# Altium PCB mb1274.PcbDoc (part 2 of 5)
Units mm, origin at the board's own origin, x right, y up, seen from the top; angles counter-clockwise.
Board outline 70 x 105 mm, 4 copper layers (Top Layer, Mid-Layer 1, Mid-Layer 2, Bottom Layer), stack 1.58 mm thick; 329 components, 271 nets, 1213 pads, 779 vias.
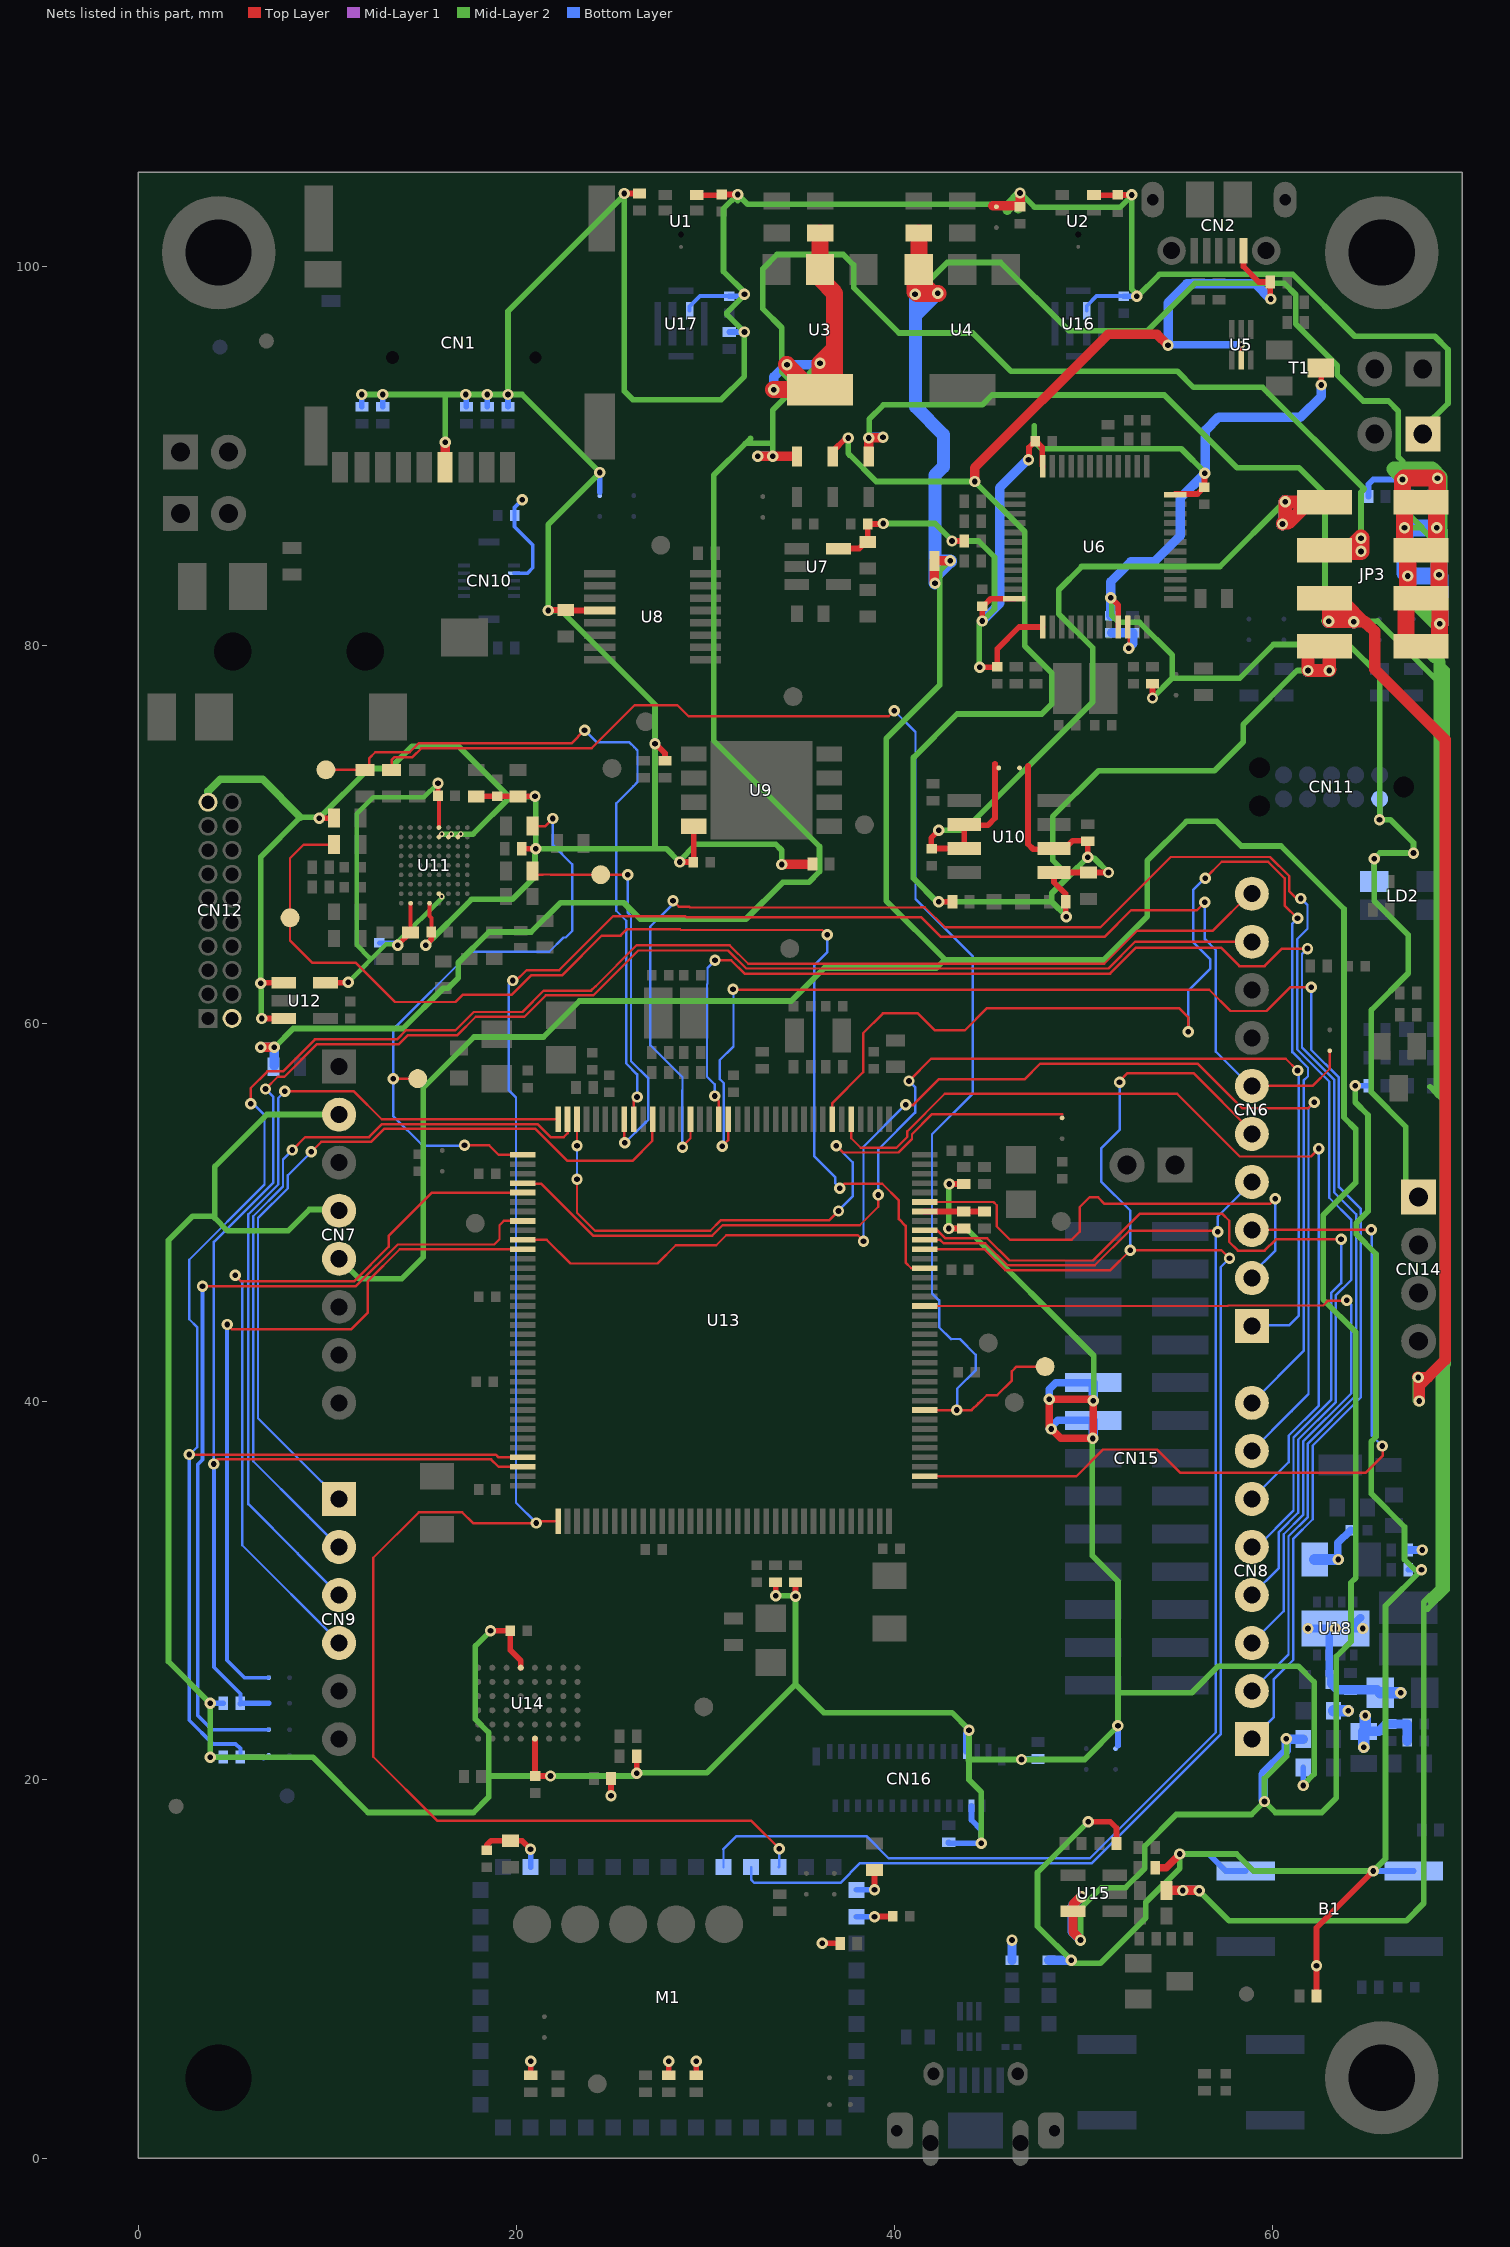
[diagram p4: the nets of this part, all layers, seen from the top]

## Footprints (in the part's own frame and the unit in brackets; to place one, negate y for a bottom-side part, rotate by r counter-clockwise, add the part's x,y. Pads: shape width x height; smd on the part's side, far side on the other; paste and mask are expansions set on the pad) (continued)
REG_SOT223-TAB [mm]
  rect 1.5x1.65 smd mask+0.05: 1(-2.3,-3.175) 2(0,-3.175) 3(2.3,-3.175)
  rect 3.5x1.65 smd mask+0.05: 4(0,3.175)
  silkscreen extent -3.35,-2.15 3.35,2.12, body extent -3.35,-3.48 3.35,3.48, height 1.8
SOLDER-BRIDGE_R0603-0R [mil]
  round 10 smd: 1(-19.69,0) 2(23.62,0)
  Top Layer region: -47.24,-19.68 -47.24,19.68 -15.75,19.68 3.94,0 -15.75,-19.68 -47.24,-19.68
  Top Layer region: -5.91,19.68 13.78,0 -5.91,-19.68 47.24,-19.68 47.24,19.68 -5.91,19.68
  silkscreen extent -50,-23 50,23, body extent -36,-20 36,20, height 22
SWI_C&K_KSC321GLFS_BLACK [mm] "BLACK"
  rect 3.1x1 smd mask+0.05: 1(-4.45,2) 2(4.45,2) 3(-4.45,-2) 4(4.45,-2)
  silkscreen extent -3.25,-3.25 3.25,3.25, body extent -5,-3.25 5,3.25, height 3.5
SWI_C&K_KSC721GLFS_BLUE [mm] "BLUE"
  rect 3.1x1 smd mask+0.05: 1(-4.45,2) 2(4.45,2) 3(-4.45,-2) 4(4.45,-2)
  silkscreen extent -3.25,-3.25 3.25,3.25, body extent -5,-3.25 5,3.25, height 4.3
TP_SMD_1MM [mm]
  round 1 smd mask+0.05: 1(0,0)
  silkscreen extent -0.7,-0.7 0.7,0.7
TP_SMD_2MM [mm]
  round 2 smd mask+0.05: 1(0,0)
  silkscreen extent -1.2,-1.2 1.2,1.2

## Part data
B1: library part Tactile_switch_CMS_BLUE_2.25N, "Tactile_switch_CMS_BLUE_2.25N"
B2: library part Tactile_switch_CMS_BLACK_2N, "Tactile_switch_CMS_BLACK_2N"
C1 C2 C7 C9 C10 C11 C12 C15 C18 C19 C25 C26 C27 C28 C29 C31 C35 C42 C50 C51 C52 C53 C54 C56 C57 C58 C59 C60 C61 C62 C63 C65 C66 C67 C68 C71 C72 C75 C77 C79 C80 C81 C82 C87 C89: library part Cap_100nF_X7R_10%_0402, "Capacitor,100nF,16V,X7R,10%,0402,YAGEO"
C3 C4 C5 C6 C88: library part Cap_10uF_X5R_10%_0805, "Capacitor,10uF,25V,X5R,10%,0805,YAGEO"
C8: library part Cap_20pF_NPO_5%_0402, "Capacitor,20pF,50V,NPO,5%,0402,YAGEO"
C13 C16 C17 C22 C23 C30 C34 C41: library part Cap_1uF_X5R_10%_0603, "Capacitor,1uF,16V,X5R,10%,0603,YAGEO"
C14: library part Cap_10nF_X7R_10%_0603, "Capacitor,10nF,50V,X7R,10%,0603,YAGEO"
C20 C21 C78 C90: library part Cap_10pF_NPO_5%_0402, "Capacitor,10pF,50V,NPO,5%,0402,YAGEO"
C24 C32 C37 C38 C39 C76: library part Cap_4.7uF_X5R_10%_0603, "Capacitor,4.7uF,16V, X5R,10%,0603,YAGEO"
C33 C36 C40 C73 C74: library part Cap_2.2uF_X5R_10%_0603, "Capacitor,2.2uF,10V, X5R,10%,0603,YAGEO"
C43 C44: library part Cap_8.2pF_NPO_4%_0402, "Capacitor,8.2pF,50V,NPO,4%,0402,AVX"
C45 C83 C86: library part Cap_10nF_X7R_10%_0402, "Capacitor,10nF,16V,X7R,10%,0402,YAGEO"
C46 C47: library part Cap_5.1pF_NPO_-+0.25pF_0402, "Capacitor, 5.1pF, 50V, NPO, -+0.25pF, 0402, YAGEO"
C48 C49 C70: library part Cap_1uF_POL_10%_TANA, "Polarized Capacitor,1uF,16V,10%,typeA,AVX"
C55 C85: library part Cap_4.7uF_POL_10%_TANA, "Polarized Capacitor,4.7uF,16V,10%,typeA,AVX"
C64 C69: library part Cap_2.2uF_X7R_10%_1206, "Capacitor,2.2uF,16V, X7R,10%,1206,YAGEO"
C84: library part Cap_4.7uF_X7R_10%_1206, "Capacitor,4.7uF,50V, X7R,10%,1206,AVX"
CN1: library part microSD-PJS008-2003, "Memory Card Connectors MicroSD Card Conn Revrs Mnt Push-Push"
CN2: library part 1050170001, "USB-MICRO-B, 1050170001, SMT, MOLEX"
CN3 CN4 CN13: library part "Header 2 pins", "Header 2 pins"
CN5: library part MCD-00263, "Connector Jack Stereo 3.5mm, female SMT, 4 PIN"
CN6: library part "Header 10X1_Female_THT", "Header, 10-Pin, Single row, female, THT, 2.54"
CN7 CN8: library part "Header 8X1_Female_THT", "Header, 8-Pins, Single row, female, THT, 2.54"
CN9: library part "Header 6X1_Female_THT", "Header, 6-Pins, Single row, female THT, 2.54"
CN10: library part "DF37NB-10DS-0.4V (5x)", "Header, 5-Pin, Dual row"
CN11: library part Tag-10-C, "Tag_Connector Header, 10-Pin, Dual row No legs"
CN12: library part "Receptacle 10X2 TH VT 1.27mm", "20 Position Receptacle Connector 0.050\" (1.27mm) Through Hole Vertical Mount"
CN14: library part "Header 4", "Header, 4-Pin"
CN15: library part "Header TMMH 13X2 2mm (.0787\")", "26 Position Receptacle Connector 0.079\" (2.00mm) Surface Mount"
CN16: library part FH26-29S-0.3SHW, "29pins FPC connector"
CN17: library part 475900001, "USB-MICRO-AB, 47590-0001, SMT, MOLEX"
D1 D2 D3 D4: library part BAT60JFILM, "BAT60JFILM"
D5: library part STPS1L40M, "Low Drop power Schottky rectifier(1A, 40V, 0.4V)"
H1 H2 H3 H4: library part "POSITION HOLE C6D3R5"
JP1 JP2: library part TSW-102-07-x-S, "Connector jumper 1 position"
JP3: library part Header_4X2_SMD, "Header, 4-Pins, Double row Vertical, SMD, 2.54"
L1 L2 L3 L5 L6 L7 L8: library part BEAD_600R_350MA_0603, "Bead,600R,350mA,0603"
L4: library part Ind_4.7uH_1A_30%, "FIXED IND 4.7UH 1A 180 MOHM 30% SMD"
LD1 LD4 LD8: library part LED_red, "LED, Red, 0603"
LD2: library part LD_BICOLOR_CMS, "Bicolor Led"
LD3 LD5 LD6 LD7: library part LED_green, "LED, Green, 0603"
M1: library part ISM43362-M3G-L44-E, "WIFI Module ISM43362-M3G-L44-E: IEEE802.11 b/g/n integrated Antenna"
R1 R2 R13 R16 R17 R20 R21 R27 R30 R31 R52 R53 R54 R55 R60 R62 R71 R72 R74 R75 R76 R77 R78 R80: library part Res_10K_1%_0402, "Resistor,10K,0402,1%,YAGEO"
R3 R14 R18 R36 R41 R70 R88 R98 R99 R100 R103 R105 R109: library part Res_100K_1%_0402, "Resistor,100K,0402,1%,YAGEO"
R4: library part Res_1K5_1%_0402, "Resistor,1K5,0402,1%,YAGEO"
R5: library part Res_36K_1%_0402, "Resistor,36K,0402,1%,YAGEO"
R6 R8: library part Res_100_1%_0402, "Resistor,100R,0402,1%,YAGEO"
R7 R51: library part Res_56_1%_0402, "Resistor,56R,0402,1%,YAGEO"
R9 R86 R87: library part Res_4K7_1%_0402, "Resistor,4K7,0402,1%,YAGEO"
R10 R56 R57 R102 R104: library part Res_2K7_1%_0402, "Resistor,2K7,0402,1%,YAGEO"
R11 R40 R44 R45 R46 R47 R48 R49 R50 R59 R61 R63 R65: library part Res_0_5%_0402, "Resistor,0R,0402,5%,YAGEO"
R12 R15 R19 R22 R23 R25 R26 R28 R29 R33 R43 R58 R67 R79: library part Res_0_5%_0603, "Resistor,0R,0603,5%,YAGEO"
R24 R39: library part Res_2K2_1%_0402, "Resistor,2K2,0402,1%,YAGEO"
R32 R35: library part Res_20_1%_0402, "Resistor,20R,0402,1%,YAGEO"
R34 R38 R93 R97 R107: library part Res_330_1%_0402, "Resistor,330R,0402,1%,YAGEO"
R37 R73 R94 R106 R108: library part Res_1K_1%_0402, "Resistor,1K,0402,1%,YAGEO"
R42 R64 R66 R68 R69 R81 R82 R83 R84 R85: library part Res_47K_1%_0402, "Resistor,47K,0402,1%,YAGEO"
R89 R90 R91 R92: library part Res_22_1%_0603, "Resistor,22R,0603,1%,Yageo"
R95: library part Res_1K_1%_0603, "Resistor,1K,0603,1%,YAGEO"
R96: library part Res_510_1%_0402, "Resistor,510R,0402,1%,YAGEO"
R101: library part Res_10_1%_0603, "Resistor,10R,0603,1%,ROHM,1/4W"
SB1 SB2 SB5 SB6 SB7 SB8 SB9 SB14 SB15 SB16 SB17 SB18 SB19 SB21 SB22: library part SB_ON, "Solder Bridge ON"
SB3 SB4 SB10 SB11 SB12 SB13 SB20 SB23 SB24: library part SB_OFF, "Solder Bridge OFF"
T1 T2 T3: library part 9013-SOT23, "NPN Bipolar Transistor"
TP1 TP2 TP3 TP4 TP5 TP6 TP7 TP8 TP9 TP10 TP11 TP12 TP13 TP14 TP15 TP16 TP22: library part "TP 1mm", "Test Point"
TP17 TP18 TP19 TP20 TP21: library part "TP 2mm", "Test Point"
U1 U2: library part MP23DB01MMTR, "MEMS audio sensor, omnidirectional digital microphone"
U3: library part LD1117S50TR, "IC REG LDO 5V 0.8A SOT223"
U4: library part LD1117S33TR, "LOW DROP FIXED AND ADJUSTABLE POSITIVE VOLTAGE REGULATORS (3.3 Volts)"
U5 U19: library part USBLC6-2P6, "USB ESD protection"
U6: library part STM32F103CBT6, "Medium-density performance line ARM-based 32-bit MCU with 128KB Flash"
U7: library part LD3985M33R, "Ultra low drop-low noise BiCMOS voltage, regulators low ESR capacitors compatible"
U8: library part TS3A44159PWR, "SPDT analog switch 4-Channel 2:1 bidirectional"
U9: library part N25Q128A13EF840F, "128Mb, 3V, Multiple I/O Serial Flash Memory, Quad/Dual"
U10: library part ST890CDR, "1.2 A current limited high-side power switch with thermal shutdown"
U11: library part WM8994ECS/R, "Multi-Channel Audio Hub CODEC for Smartphones"
U12: library part LD3985M18R, "Ultra low drop-low noise BiCMOS voltage, regulators low ESR capacitors compatible"
U13: library part STM32F413ZHT6U, "STM32 Tiny Manta 1M5 LQFP144 (STM32F413ZHT6U)"
U14: library part IS66WV51216EBLL-55BLI, "IC SRAM 8MBIT 55NS 48MINIBGA 6mm x 8mm"
U15: library part STMPS2141STR, "Enhanced single channel power switches"
U16 U17: library part MP34DT01TR-M, "MEMS audio sensor, omnidirectional digital microphone"
U18: library part STLD40DPUR, "White LED power supply for large display backlight, QFN8"
U20: library part ESDALC6V1-1U2, "Dual Transil array for ESD protection"
U21: library part MCD-00251, "High power transient voltage suppressor, 7V breakdown", Manuf_1=STM, Manuf_Part_1=ESDA7P60-1U1M
X1 X2: library part XTAL_8M_NX3225GD, "Crystal 8Mhz, 8pF, -+50PPM, SMD"
X3: library part XTAL_32K_NX3215SA, "Crystal 32.768kHz, 6pF, -+20PPM, R=50K, SMD"

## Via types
v1: diameter 0.6, hole 0.3, Top Layer to Bottom Layer, tented both sides, 574 vias
v2: diameter 0.4, hole 0.2, Top Layer to Bottom Layer, tented both sides, 125 vias
v3: diameter 0.8, hole 0.4, Top Layer to Bottom Layer, tented both sides, 49 vias
v4: diameter 0.3, hole 0.15, Top Layer to Bottom Layer, tented both sides, 31 vias

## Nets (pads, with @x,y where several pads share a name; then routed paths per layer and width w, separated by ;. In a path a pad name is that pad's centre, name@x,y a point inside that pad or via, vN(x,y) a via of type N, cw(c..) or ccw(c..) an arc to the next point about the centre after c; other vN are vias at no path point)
1V8: C26.2 C37.2 C82.2 U11.D1 U11.D8 U11.G9 U12.5 | length 27.2
  Top Layer w0.2: C37.2@14.4,64.8 U11.G9@14.4,66.35 ; U11.D8@15.9,66.85 v4(16.05,66.7) v4@16.075,66.7 ; U11.D1@15.9,70.35 C26.2@15.9,71.975
  Top Layer w0.25: v1(13.725,64.125) C37.2@14.4,64.8 ; v1(15.85,72.7) C26.2@15.85,72.025 C26.2@15.9,71.975
  Top Layer w0.3: U12.5@9.9,62.15 11.075,62.15 v1(11.1,62.175)
  Mid-Layer 1 w0.25: v1@13.725,64.1 v1(13.725,64.125)
  Mid-Layer 2 w0.25: v1(11.1,62.175) 13.1,64.175 v1@13.675,64.175 ; 12.25,63.45 11.55,64.15 11.55,71.075 12.425,71.95 15.1,71.95 v1(15.85,72.7) ; v1(13.725,64.125) 13.725,64.3 16.075,66.65 v4@16.1,66.65
  Bottom Layer w0.25: C82.2@12.75,64.25 13.6,64.25 v1(13.725,64.125)
3V3: B1.1 B1.2 C1.2 C2.2 C7.2 C16.2 C23.2 C24.2 C25.2 C28.2 C35.2 C71.2 C72.2 C73.1 C74.1 C75.2 C77.1 C79.2 C80.2 C81.1 CN1.4 CN7.2 CN7.4 CN10.9 CN12.2 CN12.19 CN15.10 CN15.12 CN16.25 CN16.26 JP2.1 L8.1 M1.2 M1.14 M1.15 R1.1 R21.2 R25.2 R30.1 R31.2 R52.2 R54.1 R56.2 R57.2 R60.2 R62.2 R64.2 R66.2 R71.2 R72.2 R74.2 R77.1 R78.1 R80.1 R81.2 R82.2 R83.2 R84.2 R85.2 R96.2 R99.2 R102.2 R103.1 R104.2 R105.1 R107.2 R108.1 SB1.2 SB14.1 SB22.1 U1.5 U2.5 U8.12 U9.8 U11.B2 U11.C2 U11.D2 U11.E9 U12.1 U12.3 U14.D6 U14.E1 U16.1 U17.1 | length 559.3
  Top Layer w0.127: v1(36.17,11.357) v1@36.177,11.35
  Top Layer w0.2: U11.E9@15.4,66.35 15.4,65.675 15.5,65.575 C35.2@15.5,64.825 ; U11.D2@15.9,69.85 v4(16.05,70) ; U11.C2@16.4,69.85 v4(16.55,70) ; U11.B2@16.9,69.85 v4(17.05,70)
  Top Layer w0.3: v1(6.475,62.125) 6.5,62.15 U12.1@7.7,62.15 ; v1(6.525,60.25) U12.3@7.7,60.25 ; v1(9.575,70.85) R25.2@10.35,70.85 ; v1(15.2,64.125) 15.5,64.425 C35.2@15.5,64.825 ; C23.2@17.875,72 C25.2@18.975,72 ; C75.2@18.425,16.275 18.425,16.55 18.65,16.775 C73.1@19.675,16.775 20.3,16.775 v1(20.74,16.335) ; v1@18.65,27.875 C71.2@19.675,27.875 ; C25.2@18.975,71.975 19,72 C24.2@20.075,72 v1(20.975,72) ; C71.2@19.675,27.85 19.675,26.85 20.225,26.3 U14.E1@20.225,25.925 ; R30.1@20.275,69.225 v1(21.025,69.225) ; R74.2@20.75,4.375 v1(20.75,5.125) ; C72.2@20.975,20.2 U14.D6@20.975,22.175 ; C72.2@21,20.2 v1(21.8,20.2) ; v1(21.675,81.825) 21.675,81.85 C16.2@22.6,81.85 ; C16.2@22.625,81.85 22.65,81.825 U8.12@24.4,81.825 ; v1(25,19.15) R62.2@25,20.075 ; v1(25.7,103.875) R1.1@26.5,103.875 ; v1(26.35,20.35) R60.2@26.35,21.25 ; v1(27.326,74.779) 27.346,74.779 27.85,74.275 R21.2@27.85,73.875 ; R77.1@28.05,4.375 v1(28.05,5.125) ; v1(28.625,68.525) C28.2@29.35,68.525 ; C28.2@29.35,68.55 29.375,68.575 U9.8@29.375,70.42 ; R78.1@29.5,4.375 v1(29.5,5.125) ; U1.5@29.538,103.789 30.839,103.789 C1.2@30.85,103.8 ; C1.2@30.85,103.825 v1(31.7,103.825) ; v1(32.052,96.555) v1@32.07,96.555 ; R56.2@33.7,30.45 33.7,29.728 v1(33.702,29.726) ; v1(34.75,29.7) R57.2@34.75,30.45 ; R31.2@35.625,68.4 R31.2@35.65,68.425 ; v1@36.177,11.35 R71.2@37.125,11.35 ; C74.1@38.925,15.225 38.925,14.191 v1(38.929,14.187) ; v1@38.937,12.775 C77.1@39.9,12.775 ; v1(42.85,49.15) R54.1@43.65,49.15 ; v1(42.875,51.5) R52.2@43.65,51.5 ; C7.2@46.525,103.225 C7.2@46.575,103.175 ; v1(50.225,17.775) 51.4,17.775 51.725,17.45 R64.2@51.725,16.625 ; U2.5@50.538,103.789 51.889,103.789 C2.2@51.9,103.8 ; C2.2@51.8,103.8 C2.2@51.9,103.8 ; v1(52.525,103.8) C2.2@51.9,103.8 ; R72.2@62.3,8.575 v1(62.3,10.175) 62.3,12.175 v1(65.3,15.175)
  Top Layer w0.4: v1@48.175,40.101 48.175,38.65 v1(48.275,38.55) 48.775,38.05 v1(50.475,38.05) ; v1(48.177,40.127) 50.423,40.127 v1@50.475,40.075 ; v1@50.45,38.075 50.5,38.125 v1(50.5,40.05) ; R66.2@53.775,15.35 54.35,15.35 v1(55.075,16.075)
  Top Layer w0.5: CN1.4@16.225,89.4 v1(16.225,90.725) ; v1(34.025,68.4) R31.2@35.625,68.4 ; 45.175,103.225 C7.2@46.525,103.225 ; C7.2@46.625,103.175 v1(46.625,103.9)
  Mid-Layer 1 w0.3: v1@33.7,29.724 v1(33.702,29.726)
  Mid-Layer 2 w0.3: v1@3.775,21.275 3.8,21.3 v1(3.8,24.05) 1.6,26.25 1.6,48.525 2.875,49.8 4.05,49.8 ; v1(3.8,21.2) 9.225,21.2 12.15,18.275 17.725,18.275 18.525,19.075 18.525,20.175 ; v1(6.475,62.125) 6.475,68.8 8.575,70.9 v1@9.55,70.9 ; v1@6.5,62.125 6.5,60.275 v1(6.525,60.25) ; v1@9.6,70.875 12.2,73.475 13.3,73.475 14.475,74.65 16.925,74.65 19.6,71.975 19.675,71.975 ; CN7.2@10.6,55.175 6.8,55.175 4.05,52.425 4.05,49.8 ; CN7.4@10.725,50.15 9.05,50.15 7.925,49.025 4.725,49.025 4.05,49.7 4.05,49.8 ; v1(11.825,93.25) v1(12.925,93.25) 16.25,93.25 ; v1(15.2,64.125) 17.625,66.55 19.775,66.55 20.975,67.75 v1@20.975,69.2 ; v4(16.05,70) v4(16.55,70) v4(17.05,70) 17.7,70 19.675,71.975 ; v1(16.225,90.725) 16.225,93.225 16.25,93.25 ; v1@17.3,93.25 16.25,93.25 ; v1(17.325,93.25) v1(18.45,93.25) v1(19.55,93.25) ; v1@18.6,27.85 17.825,27.075 17.825,23.2 18.525,22.5 18.525,20.175 ; v1@20.95,71.975 19.675,71.975 ; v1@21,69.225 v1(21.025,69.225) ; v1@21.025,71.975 v1(21.025,69.225) ; v1@24.4,89.1 21.675,86.375 v1(21.675,81.825) 22.35,81.825 27.325,76.85 v1@27.325,74.85 ; v1@24.45,89.1 20.3,93.25 v1(19.55,93.25) ; v1(25.7,103.875) 25.7,93.425 26.15,92.975 30.825,92.975 32.05,94.2 v1@32.05,96.556 ; v1@25.7,103.925 25.7,103.8 19.55,97.65 v1(19.55,93.25) ; v1@26.35,20.375 30.075,20.375 34.75,25.05 ; v1@26.375,20.425 26.15,20.2 v1(21.8,20.2) 18.55,20.2 18.525,20.175 ; v1(27.326,74.779) 27.326,69.276 27.275,69.225 ; v1@28.575,68.55 v1@28.587,68.562 ; v1(28.625,68.525) v1@28.587,68.562 ; 31.7,103.5 v1(31.7,103.825) ; v1@32.05,96.6 v1@32.05,96.556 ; v1@32.05,98.5 31.125,97.575 31.125,97.481 v1@32.05,96.556 ; v1(32.052,96.555) v1@32.05,96.556 ; v1@32.1,98.6 30.95,99.75 30.95,103.075 v1(31.7,103.825) ; v1(33.702,29.726) 34.724,29.726 v1(34.75,29.7) ; v1(34.025,68.4) 34.025,69.15 33.7,69.475 29.5,69.475 v1@28.587,68.562 ; v1@34.825,29.625 v1(34.75,29.7) ; v1@42.95,51.5 42.85,51.4 v1(42.85,49.15) 43.8,49.15 50.525,42.425 v1@50.525,40.1 ; 43.9,21.025 43.925,21.05 ; v1(44.575,16.65) 44.575,19.35 43.925,20 43.925,21.05 ; v1@46.55,103.975 45.875,103.3 32.225,103.3 v1(31.7,103.825) ; v1(46.625,103.9) 46.641,103.9 47.388,103.153 51.928,103.153 v1@52.525,103.75 ; v1(50.225,17.775) 47.55,15.1 47.55,12.25 49.5,10.3 50.875,10.3 53.275,12.7 53.275,13.525 55.075,15.325 v1(55.075,16.075) 58.075,16.075 58.975,15.175 v1(65.3,15.175) 65.95,15.825 65.95,29.2 v1(67.85,31.1) 67.5,31.1 66.95,31.65 66.95,33.375 65.201,35.124 65.201,37.891 65.45,38.14 65.45,47.8 64.4,48.85 64.4,49.434 65.025,50.059 65.025,55.15 64.35,55.825 v1(64.35,56.7) ; v1@50.45,38.125 50.45,31.85 51.8,30.5 51.8,24.6 ; v1(50.475,38.05) 50.475,39.975 v1@50.5,40 ; v1@51.825,22.85 v1@51.812,22.838 ; v1(52.525,103.8) v1@52.525,103.75 ; v1@52.575,103.8 v1@52.525,103.75 ; v1@52.8,98.4 54,99.6 61.05,99.6 64.325,96.325 68.55,96.325 69.25,95.625 69.25,92.775 67.92,91.445 JP2.1@67.92,91.15 ; v1@52.875,98.475 52.525,98.825 v1@52.525,103.75 ; v1@61.55,19.75 v1@61.625,19.75 ; v1@61.6,19.725 62.175,20.3 62.175,25.175 61.35,26 57.1,26 55.7,24.6 51.8,24.6 ; v1(21.025,69.225) 27.275,69.225 ; 27.275,69.225 27.925,69.225 v1@28.587,68.562 ; 34.75,25.05 v1(34.75,29.7) ; 34.75,25.05 36.25,23.55 43.025,23.55 43.925,22.65 v1(43.925,22.625) 43.925,21.05 ; 43.925,21.05 43.95,21.075 v1(46.7,21.075) 50.05,21.075 v1@51.812,22.838 ; 51.8,24.6 v1(51.8,22.85) v1@51.812,22.838
  Mid-Layer 2 w0.4: CN12.19@3.69,71.69 3.69,72.265 4.325,72.9 6.575,72.9 8.575,70.9
  Mid-Layer 2 w0.5: 45.95,103 v1@46.625,103.675 ; 46.525,103.075 46.625,103.175 v1@46.625,103.675 ; v1(46.625,103.9) v1@46.625,103.675
  Bottom Layer w0.127: v1(20.74,16.335) v1@20.747,16.328 ; v1@38.922,12.76 v1(38.929,12.767) ; v1@38.922,14.18 v1(38.929,14.187)
  Bottom Layer w0.2: CN10.9@19.875,83.8 20.575,83.8 20.862,84.088 20.862,85.288 19.9,86.25 C81.1@19.9,86.85 19.9,87.275 v1(20.3,87.675) v1@20.2,87.675 ; U17.1@29.15,97.675 29.15,97.9 29.7,98.45 C80.2@31.25,98.45 ; U16.1@50.15,97.675 50.15,97.925 50.675,98.45 C79.2@52.1,98.45
  Bottom Layer w0.3: v1(3.8,21.2) R104.2@4.5,21.2 ; v1(3.8,24.05) R102.2@4.5,24.05 ; R85.2@11.825,92.6 v1(11.825,93.25) ; R84.2@12.925,92.6 v1(12.925,93.25) ; v1(17.325,93.25) 17.35,93.25 R83.2@17.35,92.6 ; R82.2@18.45,92.6 v1(18.45,93.25) ; R81.2@19.55,92.6 v1(19.55,93.25) ; M1.2@20.747,15.38 v1@20.747,16.328 ; 24.4,88.075 v1(24.4,89.125) ; R80.1@31.25,96.55 32.047,96.55 v1(32.052,96.555) ; C80.2@31.25,98.45 32.05,98.45 32.052,98.452 v1(32.052,98.555) ; M1.15@37.974,12.76 v1@38.922,12.76 ; M1.14@37.974,14.18 v1@38.922,14.18 ; R105.1@42.85,16.7 42.825,16.675 42.85,16.65 v1(44.575,16.65) 44.575,17.36 44.06,17.875 CN16.26@44.06,18.625 ; CN16.25@43.76,21.5 43.76,22.435 v1@43.925,22.6 ; v1(46.7,21.075) 46.7,21.1 R103.1@47.575,21.1 ; v1(50.475,38.05) v1@50.5,38.075 ; 51.8,21.8 v1(51.8,22.85) ; C79.2@52.1,98.45 v1(52.8,98.45) ; v1(55.075,16.075) 56.6,16.075 57.5,15.175 B1.2@58.55,15.175 ; v1(61.6,19.7) L8.1@61.6,20.65 ; v1(64.35,56.7) R96.2@65.05,56.7 ; v1(65.3,15.175) B1.1@67.45,15.175 ; R99.2@67.15,31.1 v1(67.85,31.1)
  Bottom Layer w0.4: v1(48.177,40.127) 48.175,40.129 48.175,40.65 48.525,41 CN15.10@50.5,41 ; v1(48.275,38.55) 48.175,38.55 48.625,39 CN15.12@50.5,39
  Bottom Layer w0.5: R108.1@46.2,10.45 v1(46.2,11.525) ; R107.2@48.15,10.45 v1(49.325,10.45) ; v1@50.5,38.075 CN15.12@50.5,39 ; v1(50.5,40.05) CN15.10@50.5,41
  other v1: 18.625,27.875
3V3_ST_LINK: C9.2 C10.2 C12.2 C13.2 C15.2 C19.2 CN11.1 CN14.1 LD2.4 R11.2 R18.2 R87.1 T1.3 U6.1 U6.9 U6.24 U6.36 U6.48 U7.5 | length 128.1
  Top Layer w0.3: U7.5@37.025,85.1 38.125,85.1 C13.2@38.425,85.4 ; C13.2@38.575,85.45 C12.2@38.575,86.325 ; C12.2@38.575,86.4 39.375,86.4 v1(39.4,86.425) ; v1(43.025,85.5) R11.2@43.675,85.5 ; v1(44.5,78.825) 45.4,78.825 C19.2@45.425,78.85 ; v1(44.625,81.275) C15.2@44.625,82.05 ; C15.2@44.775,82.15 45.075,82.45 U6.48@46.325,82.45 ; C19.2@45.425,78.875 45.425,79.8 46.575,80.95 U6.1@47.825,80.95 ; v1@47.1,89.8 47.1,90.45 C9.2@47.425,90.775 47.425,90.825 47.793,90.457 47.793,89.482 U6.36@47.825,89.45 ; v1(51.425,82.5) 51.825,82.1 U6.9@51.825,80.95 ; v1(53.625,77.2) R18.2@53.625,77.95 ; U6.24@54.825,87.95 54.825,87.982 56.007,87.982 C10.2@56.375,88.35 56.375,89.025 v1@56.4,89.05 ; T1.3@62.525,94.65 62.55,94.625 v1(62.55,93.75)
  Mid-Layer 1 w0.3: v1(39.4,86.425) v1@39.45,86.425
  Mid-Layer 2 w0.3: v1(39.4,86.425) 42.125,86.425 v1@43.025,85.525 ; v1(43.025,85.5) 44.425,85.5 45.275,84.65 45.275,81.9 v1@44.675,81.3 ; v1@44.475,78.85 44.475,81.125 v1(44.625,81.275) ; 47.375,91.6 47.375,90.775 47.775,90.375 55.15,90.375 v1@56.425,89.1 ; v1@51.475,82.55 51.475,81.575 51.85,81.2 52.95,81.2 54.675,79.475 54.675,78.25 ; v1(53.625,77.2) 54.675,78.25 ; v1(65.635,70.76) v1@65.65,70.76 ; v1@65.65,70.75 v1@65.65,70.76 ; CN14.1@67.7,50.81 67.025,51.485 67.025,54.525 65.2,56.35 65.2,60.7 67.15,62.65 67.15,64.675 65.35,66.475 v1(65.35,68.7) 65.65,69 v1(67.425,69) 67.425,69.55 66.215,70.76 v1@65.65,70.76 ; 54.675,78.25 58.25,78.25 60.025,80.025 64,80.025 65.65,78.375 v1@65.65,70.76
  Bottom Layer w0.3: LD2.4@65.35,67.5 v1(65.35,68.7) ; v1(65.635,70.76) 65.64,70.76 CN11.1@65.64,71.865
  Bottom Layer w0.5: v1(44.625,81.275) 45.55,82.2 45.55,88.325 47.025,89.8 v1(47.075,89.8) ; R87.1@51.425,81.55 v1(51.425,82.5) 51.425,83.35 52.475,84.4 53.725,84.4 55.1,85.775 55.1,87.775 v1(56.4,89.075) ; v1@56.425,89.075 56.425,91.35 57.125,92.05 61.45,92.05 62.55,93.15 v1(62.55,93.75)
5V: C5.2 CN7.5 D4.1 JP3.2 JP3.4 JP3.6 JP3.8 L6.1 R97.1 U4.3 U15.5 | length 306.7
  Top Layer w0.3: v1(41.075,98.55) 41.175,98.6 41.135,98.63 v1@41.075,98.675 ; U4.3@41.275,99.85 U4.3@41.325,99.8 ; v1@42.93,84.455 v1(42.935,84.45) ; v1(49.825,11.525) v1@49.825,11.55 ; JP3.2@66.85,87.57 66.84,87.56 JP3.2@67.825,87.56 ; JP3.4@66.95,85.075 67.005,85.02 JP3.4@67.825,85.02 ; JP3.8@67.825,79.94 68.79,79.94 JP3.8@68.8,79.95 ; JP3.6@67.825,82.48 68.605,82.48 JP3.6@68.775,82.65 ; v1@68.8,81.125 v1(68.825,81.125)
  Top Layer w0.5: U4.3@41.075,99.65 U4.3@41.275,99.85 41.275,99.6 v1(42.275,98.6) ; v1(42.125,83.275) 42.1,83.3 D4.1@42.1,84.455 v1@42.93,84.455 ; v1@49.825,11.55 49.425,11.95 U15.5@49.425,13.05 49.425,13.4 49.85,13.825 v1(49.875,13.825)
  Top Layer w0.9: v1@41.075,98.675 U4.3@41.075,99.65 ; v1@41.175,98.6 v1(42.275,98.6) ; U4.3@41.275,99.85 C5.2@41.275,101.775 ; JP3.2@66.85,87.57 v1(66.85,88.75) 66.925,88.825 v1@68.65,88.825 ; JP3.4@66.95,85.075 v1(66.95,86.2) 66.95,87.325 JP3.2@66.975,87.35 ; JP3.6@67.025,82.45 67.025,80.05 67.05,80.025 67.74,80.025 JP3.8@67.825,79.94 ; JP3.4@67.1,84.975 67.125,84.95 v1(67.125,83.65) 67.125,82.83 67.555,82.4 67.73,82.575 JP3.6@67.825,82.48 ; JP3.4@67.825,85.02 68.305,85.02 68.65,85.365 v1(68.65,86.2) 68.65,87.5 JP3.2@68.7,87.55 ; JP3.2@67.825,87.56 68.685,87.56 68.685,88.81 v1(68.7,88.825) ; JP3.6@68.775,82.65 v1(68.775,83.725) JP3.4@68.775,85 ; JP3.8@68.8,79.95 v1@68.8,81.125 ; JP3.6@68.8,82.4 68.825,82.375 v1(68.825,81.125)
  Mid-Layer 2 w0.3: CN7.5@10.62,47.55 11.672,46.498 13.939,46.498 15.075,47.634 15.075,56.6 17.75,59.275 21.425,59.275 23.325,61.175 34.525,61.175 36.275,62.925 42.2,62.925 42.625,63.35 ; v1@41.35,98.625 41.35,98.8 42.775,100.225 45.6,100.225 49.2,96.625 53.375,96.625 55.875,99.125 60.6,99.125 61.2,98.525 61.2,96.975 63.4,94.775 63.4,94.275 64.775,92.9 66.1,92.9 66.625,92.375 66.625,89.95 66.85,89.725 66.85,89.3 66.85,88.85 v1(66.85,88.75) 66.85,87.5 66.725,87.375 67.85,86.25 ; v1@42.95,84.5 42.375,83.925 42.375,77.875 39.55,75.05 39.55,66.475 42.675,63.35 51.05,63.35 53.35,65.65 53.35,68.6 55.425,70.675 57.025,70.675 58.325,69.375 60.425,69.375 63.75,66.05 63.75,55.025 64.375,54.4 ; v1(49.825,11.525) 49.825,13.2 50.925,14.3 52.2,14.3 53.225,15.325 53.225,16.5 54.887,18.162 58.862,18.162 v1(59.55,18.85) ; v1@60.725,22.1 60.725,21.25 59.55,20.075 v1(59.55,18.85) ; 64.375,54.425 64.375,54.4 ; v1(66.95,86.2) 67.825,86.2 68.825,85.2 ; v1(68.775,83.725) 68.775,81.125 68.775,81.1 v1@68.875,81 ; v1@68.825,83.575 v1@68.825,83.775 ; v1(59.55,18.85) 60.125,18.275 62.575,18.275 63.35,19.05 63.35,26.525 64.125,27.3 64.125,30.425 64.375,30.675 64.375,43.675 62.65,45.4 62.65,49.85 64.375,51.575 64.375,54.4
  Mid-Layer 2 w0.8: v1@66.85,88.85 66.4,89.3 66.85,89.3 68.4,89.3 68.825,88.875 v1@68.825,86.025 ; 67.125,82.675 68.675,81.125 68.775,81.125 v1(68.825,81.125) v1@68.825,83.575 ; v1(68.65,86.2) v1@68.825,86.025 ; v1(68.775,83.725) 68.825,83.775 68.825,85.2 v1@68.825,86.025
  Bottom Layer w0.3: v1@60.675,22.15 v1(60.7,22.175) ; R97.1@65.05,87.85 65.05,88.5 65.3,88.75 v1(66.85,88.75)
  Bottom Layer w0.4: v1(66.85,88.75) 68.625,88.75 v1(68.7,88.825)
  Bottom Layer w0.5: v1@41.025,98.525 v1@41.1,98.6 ; v1(49.825,11.525) 49.375,11.975 49.375,13.325 v1@49.9,13.85 ; v1(59.55,18.85) 59.475,18.925 59.475,20.3 60.7,21.525 v1@60.7,22.15 ; v1@60.675,22.15 v1@60.7,22.15 ; v1(60.7,22.175) v1@60.7,22.15 ; L6.1@61.6,22.15 v1@60.7,22.15
  Bottom Layer w0.7: v1@41.1,98.5 41.1,97.425 ; v1@41.1,98.6 v1(42.275,98.6) 41.1,97.425 ; v1(42.125,83.275) 42.125,83.64 ; v1(42.935,84.45) v1@42.93,84.445 ; v1@42.95,84.425 v1@42.93,84.445 ; 41.1,97.425 41.1,92.6 42.575,91.125 42.575,89.425 42.125,88.975 42.125,84.45 ; 42.125,83.64 v1@42.93,84.445 ; 42.125,83.64 42.125,84.45 ; 42.125,84.45 42.925,84.45 v1@42.93,84.445
  Bottom Layer w0.9: v1(66.95,86.2) v1@66.975,86.2 ; v1@68.7,86.15 v1(68.65,86.2) v1@68.625,86.2 ; v1@68.75,83.6 68.7,83.65 v1(67.125,83.65) 66.975,83.8 v1@66.975,86.2 ; v1@68.775,83.675 68.825,83.625 v1(68.825,81.125) ; v1(68.775,83.725) 68.775,86.05 v1@68.625,86.2 ; v1@66.975,86.2 v1@68.625,86.2
5V_ARD: C4.2 D1.1 JP3.3 R95.1 U3.2 U3.4 | length 145.9
  Top Layer w0.3: 34.52,89.97 34.525,89.975 ; U3.2@36.05,99.85 36.05,99.725 U3.2@36.125,99.65 ; JP3.3@62.65,85.025 JP3.3@62.655,85.02 ; JP3.3@62.725,84.95 JP3.3@62.655,85.02 ; JP3.3@62.725,85.02 JP3.3@62.655,85.02
  Top Layer w0.5: v1(6.475,58.725) v1@7.175,58.725 ; v1(32.75,89.975) v1(33.55,89.975) 34.525,89.975 ; 34.35,89.97 34.52,89.97 D1.1@34.825,89.97
  Top Layer w0.9: v1(33.6,93.5) U3.4@35.6,93.5 ; v1(34.3,94.825) 34.275,94.825 U3.4@35.6,93.5 ; U3.4@36.025,93.475 U3.4@36.05,93.5 ; C4.2@36.05,101.775 36.05,99.725 36.05,99.375 36.825,98.6 36.825,95.675 ; U3.4@36.925,93.625 36.825,93.725 36.825,95.675 ; JP3.3@62.725,84.95 JP3.3@63.95,84.95 ; JP3.3@62.95,84.9 63.9,84.9 JP3.3@63.95,84.95 ; U3.4@35.6,93.5 U3.4@36.05,93.5 ; U3.4@36.05,93.5 v1(36.05,94.9) 36.825,95.675 ; JP3.3@63.95,84.95 v1(64.65,85.65) v1(64.65,84.95) JP3.3@63.95,84.95
  Mid-Layer 2 w0.3: v1(7.2,58.725) 8.2,59.725 14,59.725 16.127,61.852 16.377,61.852 16.923,62.398 16.923,63.202 18.546,64.825 20.775,64.825 22.325,66.375 25.675,66.375 26.55,65.5 32.125,65.5 34.075,67.45 35.45,67.45 36.025,68.025 36.025,69.35 30.425,74.95 30.425,88.975 32.112,90.662 ; 32.375,90.925 32.112,90.662 ; v1(33.55,89.975) 33.55,90.6 ; v1@36.05,94.925 34.8,93.675 ; v1@36.1,94.975 v1@36.15,94.925 ; v1(64.65,84.95) v1(64.65,85.65) 64.65,88.075 64.825,88.25 59.45,93.625 55.8,93.625 54.95,94.475 46.15,94.475 44.125,96.5 40.225,96.5 37.825,98.9 37.825,100.1 37.275,100.65 33.775,100.65 33.025,99.9 33.025,97.775 34.025,96.775 34.025,94.45 34.8,93.675 ; 32.112,90.662 33.487,90.662 33.55,90.6 ; 33.55,90.6 33.55,92.425 34.8,93.675
  Bottom Layer w0.3: R95.1@7.15,57.7 R95.1@7.2,57.75
  Bottom Layer w0.5: v1(6.475,58.725) v1(7.2,58.725) R95.1@7.2,57.75 ; v1@32.7,89.975 v1(32.75,89.975) v1(33.55,89.975) ; v1(33.6,93.5) 33.6,94.175 v1@34.3,94.875 ; v1(34.3,94.825) 35.925,94.825 v1@36.05,94.95
  Bottom Layer w0.7: v1@64.65,84.975 v1(64.65,85.65)
5V_ST_LINK: C27.2 JP3.1 SB4.2 U10.6 U10.7 | length 46.7
  Top Layer w0.3: C27.2@41.95,69.225 41.925,69.25 41.925,69.8 v1(42.325,70.2) ; C27.2@42,69.225 42.015,69.24 U10.7@43.675,69.24 ; U10.7@43.675,69.2 U10.7@43.675,69.24 ; 45.3,73.725 45.3,70.85 44.925,70.475 43.675,70.475 U10.7@43.675,69.24 ; v1(60.65,87.575) v1@60.665,87.56
  Top Layer w0.7: v1(60.5,86.4) 60.5,86.45 v1@60.55,86.45 ; v1(60.65,87.575) 60.65,86.55 v1@60.55,86.45 ; v1@60.665,87.56 JP3.1@61.91,87.56 ; JP3.1@62.725,87.56 JP3.1@61.91,87.56 ; v1@60.55,86.45 60.8,86.45 JP3.1@61.91,87.56
  Mid-Layer 2 w0.3: v1(42.325,70.2) 43.65,70.2 43.663,70.187 50.475,77 50.475,79.85 48.675,81.65 48.675,82.925 49.875,84.125 ; 49.875,84.15 57.2,84.15 v1@60.65,87.6
  Bottom Layer w0.7: v1(60.5,86.4) 60.65,86.55 v1(60.65,87.575)
5V_USB_CHARGER: C30.2 CN2.1 D2.1 JP3.7 R2.1 R27.2 R36.2 R37.2 SB4.1 U5.5 U10.1 U10.2 | length 124.3
  Top Layer w0.2: U5.5@58.325,95.07 v2(58.325,95.875)
  Top Layer w0.3: D2.1@36.725,89.97 36.725,90.25 37.425,90.95 v1(37.55,90.95) ; v1(42.325,66.425) R36.2@43.05,66.425 ; 47.05,73.6 47.05,69.475 47.325,69.2 48.425,69.2 U10.2@48.425,69.24 48.99,69.24 49.4,69.65 R27.2@50.225,69.65 ; R37.2@49.025,66.475 49.025,66.85 48.425,67.45 U10.1@48.425,67.97 50.18,67.97 C30.2@50.225,67.925 ; R37.2@49.05,66.425 49.05,65.65 v1(49.075,65.625) ; v1(50.2,68.775) R27.2@50.2,69.625 ; C30.2@50.25,67.975 v1(51.3,67.975) ; CN2.1@58.44,100.85 58.44,100.01 59.25,99.2 R2.1@59.85,99.2 59.85,98.325 v1(59.875,98.3) ; JP3.7@62.725,79.94 JP3.7@62.975,79.69
  Top Layer w0.5: v1(44.225,88.65) 44.225,89.375 51.275,96.425 53.875,96.425 v1(54.45,95.85) ; JP3.7@61.85,79.775 62.015,79.94 JP3.7@62.725,79.94
  Top Layer w0.7: JP3.7@61.85,79.775 v1(61.85,78.65) 62.95,78.65 v1@62.975,78.675 ; v1(62.975,78.65) v1@62.975,78.675 ; JP3.7@62.975,79.69 v1@62.975,78.675 ; v1@63,78.7 v1@62.975,78.675
  Mid-Layer 2 w0.3: v1@37.575,90.925 v1(37.55,90.95) 37.55,90.125 37.6,90.075 ; 37.6,90.05 37.6,90.075 ; 40.975,74.05 40.975,74.025 ; v1@42.275,66.375 40.975,67.675 40.975,74.025 ; v1(42.325,66.425) 48.3,66.425 ; v1@49.075,65.65 48.3,66.425 ; v1(50.2,68.775) 49.2,67.775 ; v1@50.225,68.725 50.55,68.725 v1(51.3,67.975) ; v1(62.975,78.65) v1(61.85,78.65) 61.325,78.65 61.3,78.675 58.425,75.8 58.425,74.875 56.9,73.35 50.775,73.35 48.35,70.925 48.35,68.625 49.2,67.775 ; 37.6,90.075 39.025,88.65 v1(44.225,88.65) 46.875,86 46.875,80.375 46.875,79.95 48.3,78.525 48.3,76.875 47.775,76.35 43.3,76.35 40.975,74.025 ; 48.3,66.425 48.3,66.875 49.2,67.775
  Bottom Layer w0.4: v1(54.45,95.85) 54.475,95.875 v2(58.325,95.875)
  Bottom Layer w0.5: v1@54.45,95.875 54.45,98.1 55.45,99.1 59.075,99.1 v1(59.875,98.3)
  Bottom Layer w0.7: v1(61.85,78.65) v1@62.925,78.65
5V_USB_FS: D3.1 JP3.5 R67.2 | length 236.9
  Top Layer w0.3: JP3.5@62.725,82.48 JP3.5@63.025,82.18
  Top Layer w0.4: v1@39.35,90.95 39.377,90.977 v1(39.377,90.979)
  Top Layer w0.5: D3.1@38.625,89.97 v1(38.625,90.95) v1@39.35,90.95 ; R67.2@54.375,14.15 v1(55.225,14.15) 56.075,14.15 v1(56.1,14.125)
  Top Layer w0.6: JP3.5@63.025,82.18 63.955,81.25 64.005,81.2 v1@64.275,81.2 ; v1(64.275,81.225) 64.825,81.225 ; 64.275,81.725 64.325,81.725 64.825,81.225 ; 65.125,80.925 64.825,81.225 ; v1@67.65,41.3 v1(67.675,41.275) ; v1(67.725,40.025) 67.725,40.825 ; 64.825,81.225 64.875,81.225 65.375,80.725 65.375,78.725 69.1,75 69.1,42.2 68.175,41.275 ; v1(67.675,41.275) 67.725,41.225 67.725,40.825 ; v1(67.675,41.275) 68.175,41.275 ; 67.725,40.825 68.175,41.275
  Top Layer w0.7: JP3.5@62.67,82.425 JP3.5@62.725,82.48 63.52,82.48 64.275,81.725 v1@64.275,81.25 ; JP3.5@63.025,82.18 62.95,82.105 v1(62.95,81.25) 63.955,81.25 v1@64.275,81.25 ; v1(64.275,81.225) v1@64.275,81.25 ; v1@64.3,81.25 v1@64.275,81.25
  Mid-Layer 2 w0.3: v1@38.65,90.975 38.65,91.95 39.4,92.7 44.625,92.7 45.15,93.225 54.25,93.225 58.1,89.375 61.375,89.375 62.75,88 v1@62.75,81.3 ; v1(56.1,14.125) 57.675,12.55 67.05,12.55 67.975,13.475 67.975,29.4 68.75,30.175 68.75,41.95 68.963,42.163 ; v1@62.7,81.275 62.725,81.25 v1(62.95,81.25) 65.5,81.25 65.525,81.275 68.8,78 69.2,77.6 ; 68.175,29.025 69.2,30.05 69.2,42.4 ; 68.3,56.65 68.6,56.35 68.8,56.35 69.1,56.35 ; 68.325,29.425 68.963,30.063 68.963,41.85 68.963,42.163 ; 68.562,79.338 68.8,79.1 69.2,78.7 69.2,77.6 ; 69.1,42.3 68.963,42.163 ; 69.2,56.35 69.2,77.6
  Mid-Layer 2 w0.5: v1(55.225,14.15) 56.05,14.15 v1@56.1,14.1
  Mid-Layer 2 w0.6: v1(67.675,41.275) 67.675,40.075 v1(67.725,40.025) ; 68.8,56.35 69.1,56.05 ; 68.963,41.85 69.1,41.987 69.1,42.3 69.1,56.05 ; 69.1,56.35 69.1,56.05
  Mid-Layer 2 w0.65: 68.2,79.7 68.562,79.338 ; 68.8,56.35 68.8,78 68.8,79.1
  Bottom Layer w0.5: v1@38.625,90.925 38.679,90.979 v1(39.377,90.979) ; v1@55.25,14.175 55.275,14.15 56.075,14.15 v1(56.1,14.125)
  Bottom Layer w0.6: v1(67.725,40.025) v1@67.725,41.2
  Bottom Layer w0.7: v1(62.95,81.25) 64.25,81.25 v1(64.275,81.225)
AIN_1: R86.2 R87.2 U6.10 | length 3
  Top Layer w0.127: U6.10@52.325,80.8 52.378,80.747 v1(52.378,79.829)
  Bottom Layer w0.127: v1@52.325,79.825 52.374,79.825 v1(52.378,79.829)
  Bottom Layer w0.5: R87.2@51.475,80.65 R86.2@52.5,80.65 ; v1@52.325,79.825 52.575,80.075 R86.2@52.575,80.65
ARD_A0: CN9.1 U13.26 | length 42.1
  Top Layer w0.127: v1(9.15,53.2) 9.679,53.729 12.313,53.729 13.001,54.417 21.007,54.417 22.699,52.725 26.125,52.725 27.175,53.775 27.175,54.9 U13.26@27.2,54.925
  Bottom Layer w0.127: v1(9.15,53.2) 7.908,51.958 7.908,51.271 6.333,49.696 6.333,39.117 9.7,35.75 ; 9.71,35.76 CN9.1@10.62,34.85
ARD_A1: CN9.2 U13.35 | length 40
  Top Layer w0.127: v1(8.15,53.302) v1(8.15,53.302) 8.833,53.983 12.208,53.983 12.896,54.671 21.112,54.671 21.8,53.983 22.5,53.983 22.7,54.183 U13.35@22.7,54.925
  Bottom Layer w0.127: v1@8.175,53.325 7.654,52.804 7.654,51.376 6.079,49.801 6.079,36.846 8.95,33.975 ; 8.952,33.978 CN9.2@10.62,32.31
ARD_A2: CN9.3 U13.36 | length 44.5
  Top Layer w0.127: v1(7.75,56.4) 11.4,56.4 12.875,54.925 U13.36@22.2,54.925
  Bottom Layer w0.127: v1(7.75,56.4) 7.4,56.05 7.4,51.482 5.825,49.907 5.825,34.575 8.425,31.975 ; 8.42,31.97 CN9.3@10.62,29.77
ARD_A3: CN9.4 U13.41 | length 39.3
  Top Layer w0.127: v1(5.125,46.675) 5.13,46.675 5.45,46.355 11.411,46.355 13.241,48.185 13.241,48.751 15.541,51.05 U13.41@20.3,51.05
  Bottom Layer w0.127: v1(5.125,46.675) 5.5,46.3 5.5,32.4 10.62,27.28 CN9.4@10.62,27.23
ARD_A4: SB19.1 U13.47 | length 38.8
  Top Layer w0.127: v1(4.7,44.075) 4.946,43.829 11.27,43.829 12.125,44.684 12.125,46.35 13.825,48.05 15.4,48.05 U13.47@20.325,48.05
  Bottom Layer w0.2: v1(4.7,44.075) 4.7,26.325 5.625,25.4 SB19.1@6.9,25.4
ARD_A5: SB21.1 U13.44 | length 45.7
  Top Layer w0.127: v1(3.4,46.1) 11.516,46.101 13.72,48.304 18.825,48.304 19.1,48.579 19.1,49.325 19.325,49.55 U13.44@20.325,49.55
  Bottom Layer w0.2: v1(3.4,46.1) 3.4,36.925 3.15,36.675 3.15,23.4 3.9,22.65 SB21.1@6.9,22.65
ARD_D0: CN8.1 U13.18 | length 85
  Top Layer w0.127: v1(30.875,53.5) 31.2,53.825 U13.18@31.2,54.925 ; v1@31.525,61.825 31.579,61.771 56.629,61.771 57.75,60.65 59.65,60.65 60.9,61.9 v1(62.025,61.9)
  Bottom Layer w0.127: v1(30.875,53.5) 30.967,53.592 30.967,56.833 30.75,57.05 30.75,58.05 31.475,58.775 v1@31.475,61.825 ; CN8.1@58.88,22.15 59.977,23.247 ; 59.975,23.25 60.05,23.325 60.05,25.325 61.075,26.35 61.075,32.75 62.1,33.775 62.1,37.675 64.65,40.225 64.65,50.175 63.485,51.34 63.485,57.134 62.025,58.593 v1(62.025,61.9)
  other v1: 31.45,61.8
ARD_D1: CN8.2 U13.19 | length 84.7
  Top Layer w0.127: v1(30.476,56.152) 30.476,56.099 30.7,55.875 U13.19@30.7,54.925 ; v1(30.5,63.325) 31.357,63.325 32.057,62.625 51.384,62.625 52.759,64 57.25,64 58.225,63.025 59.55,63.025 ; 59.575,63.025 59.55,63.025 ; v1(61.825,63.95) 60.475,63.95 59.55,63.025
  Bottom Layer w0.127: 30.075,62.075 30.075,57.175 30.473,56.777 30.473,56.152 v1(30.476,56.152) ; 30.1,62.075 30.1,62.925 v1(30.5,63.325) ; CN8.2@58.88,24.69 60.821,26.631 60.821,32.875 61.846,33.9 61.846,37.78 64.396,40.33 64.396,49.904 63.231,51.069 63.231,57.029 61.534,58.725 61.534,63.659 v1(61.825,63.95)
ARD_D2: CN8.3 U13.128 | length 42.8
  Top Layer w0.127: U13.128@41.575,45.05 57.6,45.05 57.631,45.081 62.656,45.081 62.91,45.335 v1@63.725,45.335 ; v1@63.725,45.35 v1(63.9,45.35)
  Bottom Layer w0.127: CN8.3@58.88,27.23 60.567,28.917 60.567,32.98 61.592,34.005 61.592,37.885 64.142,40.435 64.142,45.108 v1(63.9,45.35)
ARD_D3: CN8.4 U13.22 | length 93.2
  Top Layer w0.127: v1(28.275,66.475) 28.582,66.168 29.129,66.168 29.174,66.123 41.369,66.123 41.38,66.135 41.59,66.135 42.65,65.075 50.875,65.075 54.595,68.795 59.846,68.795 60.869,67.771 60.869,66.975 61.269,66.575 61.5,66.575 v1(61.475,66.6) ; v1(28.776,53.452) 28.776,53.501 29.2,53.925 U13.22@29.2,54.925
  Bottom Layer w0.127: v1(28.275,66.475) 28.275,66.316 27.07,65.111 27.07,58.848 28.775,57.143 28.775,56.475 28.774,53.45 v1(28.776,53.452) ; CN8.4@58.88,29.77 60.313,31.203 60.313,33.1 61.338,34.125 61.338,37.991 63.325,39.978 63.325,45.625 64.142,46.442 64.142,49.608 62.977,50.774 62.977,56.923 61.28,58.619 61.28,64.455 61.825,65 61.825,66.25 v1(61.475,66.6)
ARD_D4: CN8.5 U13.136 | length 43.8
  Top Layer w0.127: U13.136@41.575,49.05 42.256,49.05 42.681,48.625 44.893,48.625 46.06,47.458 50.474,47.458 52.941,49.925 57.325,49.925 57.687,49.563 57.687,48.438 58.145,47.98 59.554,47.98 60.15,48.575 v1(63.6,48.575)
  Bottom Layer w0.127: CN8.5@58.88,32.31 59.164,32.31 61.084,34.23 61.084,38.096 63.071,40.083 63.071,45.73 63.6,46.259 v1(63.6,48.575)
ARD_D5: CN8.6 U13.5 | length 48.8
  Top Layer w0.127: U13.5@37.7,54.925 37.7,53.925 38.204,53.421 40.089,53.421 40.658,53.99 40.658,54.283 42.648,56.273 54.927,56.273 55.575,55.625 58.245,52.955 62.005,52.955 v1(62.425,53.375)
  Bottom Layer w0.127: CN8.6@58.88,34.85 60.83,36.8 60.83,38.201 62.425,39.796 v1(62.425,53.375)
ARD_D6: CN8.7 U13.46 | length 70.9
  Top Layer w0.127: U13.46@20.325,48.55 21.6,48.55 22.85,47.3 27.45,47.3 28.417,48.267 30.56,48.267 31.089,48.796 38.054,48.796 v1@38.375,48.475 ; v1(40.575,55.7) v1@40.65,55.7 ; v1@40.65,55.675 40.972,55.675 42.347,57.05 46.431,57.05 46.447,57.035 46.853,57.035 47.69,57.871 56.004,57.871 58.359,55.516 61.866,55.516 v1(62.175,55.825)
  Bottom Layer w0.127: v1(38.35,48.475) 38.35,53.475 v1(40.575,55.7) ; CN8.7@58.88,37.39 60.982,39.493 ; 60.975,39.5 61.875,40.4 61.875,55.525 v1(62.175,55.825)
ARD_D7: CN8.8 U13.7 | length 68.6
  Top Layer w0.127: U13.7@36.7,54.925 36.7,55.784 38.325,57.409 38.325,59.475 39.375,60.525 41.225,60.525 42.125,59.625 43.7,59.625 44.875,60.8 55.037,60.8 55.525,60.312 v1(55.525,59.55) ; v1(56.425,67.675) 57.291,68.541 59.741,68.541 60.615,67.666 60.615,66.235 v1(61.3,65.55)
  Bottom Layer w0.127: v1(55.525,59.55) 55.525,61.725 56.675,62.875 56.675,63.4 55.775,64.3 55.775,67.05 56.4,67.675 v1(56.425,67.675) ; CN8.8@58.88,39.93 61.621,42.671 61.621,56.971 61.85,57.2 61.85,57.65 61.026,58.474 61.026,65.277 v1(61.3,65.55)
ARD_D8: CN6.1 U13.40 | length 65
  Top Layer w0.127: U13.40@20.615,51.525 21.3,51.525 24.05,48.775 30.35,48.775 30.9,49.325 38.15,49.325 39.125,50.3 v1(39.125,50.925) ; v1(40.75,56.95) 41.925,58.125 60.675,58.125 v1(61.3,57.5) v1@61.325,57.5
  Bottom Layer w0.127: v1(39.125,50.925) 39.125,53.325 41.075,55.275 41.075,56.625 v1@40.775,56.925 ; v1@40.75,56.925 v1(40.75,56.95) ; CN6.1@58.775,44.025 60.85,44.025 61.367,44.542 61.367,57.433 v1(61.3,57.5)
ARD_D9: CN6.2 U13.139 | length 26.8
  Top Layer w0.127: U13.139@41.575,50.55 45.225,50.55 45.396,50.379 45.396,49.254 46.096,48.554 49.354,48.554 49.775,48.975 49.775,50.275 50.3,50.8 50.75,50.8 51.096,50.454 59.854,50.454 v1(60.125,50.725)
  Bottom Layer w0.127: CN6.2@58.85,46.375 CN6.2@58.85,46.53 ; CN6.2@58.88,46.53 58.88,46.739 60.125,47.984 v1(60.125,50.725)
ARD_D10: CN6.3 U13.110 | length 44.1
  Top Layer w0.127: U13.110@41.575,36.05 49.606,36.05 51.02,37.464 53.87,37.464 55.105,36.229 64.895,36.229 65.808,37.142 65.808,37.642 65.798,37.652 v1(65.778,37.652) ; CN6.3@59.05,49.1 59.075,49.075 v1(65.2,49.075)
  Bottom Layer w0.127: v1(65.2,49.075) v1@65.237,49.037 ; v1@65.225,49.025 65.225,38.2 v1@65.775,37.65
ARD_D11: CN6.4 M1.9 U13.135 | length 77.3
  Top Layer w0.127: U13.135@41.575,48.55 42.397,48.55 42.576,48.371 44.788,48.371 45.955,47.204 50.579,47.204 52.4,49.025 57.125,49.025 v1(57.075,48.975)
  Bottom Layer w0.127: M1.9@30.946,15.38 30.946,16.328 30.939,16.335 31.629,17.025 38.5,17.025 39.675,15.85 50.325,15.85 56.975,22.5 56.975,48.875 v1(57.075,48.975) 57.075,49.775 CN6.4@58.875,51.575
ARD_D12: CN6.5 M1.10 U13.134 | length 90
  Top Layer w0.127: U13.134@41.575,48.05 44.75,48.05 45.85,46.95 51.4,46.95 v1(52.453,48.002) 57.273,48.002 v1(57.7,47.575) ; v1(51.888,56.875) 51.85,56.913 52.3,57.363 55.794,57.363 58.88,54.277 CN6.5@58.88,54.15 ; CN6.5@58.902,54.173 CN6.5@58.925,54.15
  Bottom Layer w0.127: M1.10@32.403,15.38 32.403,14.722 32.575,14.55 37.125,14.55 38.171,15.596 50.43,15.596 57.229,22.395 57.229,47.104 v1(57.7,47.575) ; 50.912,51.638 52.45,50.1 52.45,49.55 ; 50.925,51.65 50.925,53.4 51.888,54.363 v1(51.888,56.875) ; v1(52.453,48.002) 52.453,49.55
ARD_D13: CN6.6 M1.11 SB5.1 U13.73 | length 130.8
  Top Layer w0.127: v1(19.81,62.265) 19.9,62.175 20.529,62.804 22.254,62.804 25.11,65.66 28.919,65.66 28.963,65.615 41.391,65.615 42.44,64.567 51.085,64.567 52.493,65.975 55.975,65.975 v1(56.4,66.4) ; v1(21.05,33.575) 17.7,33.575 17.134,34.141 14.831,34.141 12.429,31.738 12.429,21.221 15.822,17.828 32.422,17.828 v1(33.9,16.35) ; v1@21.125,33.675 U13.73@22.2,33.675 ; CN6.6@58.825,56.65 CN6.6@58.85,56.675 ; CN6.6@58.88,56.69 62.09,56.69 63,57.6 SB5.1@63,58.55
  Bottom Layer w0.127: v1(19.81,62.265) 19.6,62.056 19.6,56.45 19.975,56.075 19.975,34.65 v1(21.05,33.575) ; M1.11@33.86,15.38 33.9,15.42 v1(33.9,16.35) ; v1(56.4,66.4) 56.4,64.45 56.975,63.875 56.975,58.5 CN6.6@58.825,56.65
ARD_D14: CN6.9 R102.1 SB20.1 U13.70 | length 108.5
  Top Layer w0.127: v1@4.166,36.941 18.66,36.941 19.05,36.55 19.3,36.55 U13.70@20.325,36.55 ; v1(6.725,56.525) 7.375,57.175 7.725,57.175 9.446,58.896 13.779,58.896 14.258,59.375 16.875,59.375 17.842,60.342 20.417,60.342 21.55,61.475 24.059,61.475 26.434,63.85 31.191,63.85 32.145,62.896 51.296,62.896 52.71,64.31 CN6.9@58.88,64.31 ; CN6.9@58.895,64.295 CN6.9@58.9,64.3
  Bottom Layer w0.127: v1(4,36.701) 4,48.441 7.146,51.587 7.146,56.104 v1(6.725,56.525)
  Bottom Layer w0.2: v1(4,36.701) 4,25.95 5.4,24.55 R102.1@5.4,24.05
  Bottom Layer w0.3: R102.1@5.4,24.025 5.425,24.05 SB20.1@6.9,24.05
ARD_D15: CN6.10 R104.1 SB24.1 U13.69 | length 116.7
  Top Layer w0.127: v1(2.7,37.2) 2.705,37.195 18.905,37.195 ; v1(5.95,55.75) 5.95,56.575 6.83,57.455 7.645,57.455 9.341,59.15 13.674,59.15 14.153,59.629 16.77,59.629 17.737,60.596 20.312,60.596 21.445,61.729 23.947,61.729 24.181,61.962 24.188,61.962 26.354,64.129 31.271,64.129 32.25,63.15 51.075,63.15 52.825,64.9 56.825,64.9 58.825,66.9 CN6.10@58.925,66.9 ; 18.988,37.113 18.906,37.195 ; U13.69@20.325,37.05 19.05,37.05 18.905,37.195
  Bottom Layer w0.127: v1@2.725,37.2 3.11,37.584 3.11,43.94 2.7,44.35 2.7,47.5 6.675,51.475 6.675,55.15 6.075,55.75 v1(5.95,55.75)
  Bottom Layer w0.2: v1(2.7,37.2) 2.7,23.15 3.95,21.9 5.15,21.9 5.4,21.65 R104.1@5.4,21.2
  Bottom Layer w0.3: R104.1@5.4,21.2 6.6,21.2 ; 6.625,21.175 6.6,21.2 ; 6.65,21.2 6.6,21.2
B_USER: SB6.1 U13.34 | length 36.8
  Top Layer w0.127: v1(23.2,51.75) 23.2,49.984 24.155,49.029 30.245,49.029 30.795,49.579 36.529,49.579 v1(37.025,50.075) ; v1(23.2,53.525) U13.34@23.2,54.925 ; v1(36.9,53.525) 37.258,53.167 40.195,53.167 40.912,53.884 40.912,54.137 41.975,55.2 48.85,55.2
  Bottom Layer w0.127: v1(23.2,51.75) v1(23.2,53.525) ; v1(36.9,53.525) 37.775,52.65 37.775,50.85 37.025,50.1 v1(37.025,50.075)
BLGND: C83.1 C84.1 C85.2 C86.1 C87.1 C88.1 C89.1 L5.2 R98.1 R100.1 R101.1 U18.3 U18.9 | length 20.2
  Bottom Layer w0.4: v1(61.85,28) v1(63.3,28) ; U18.9@62.975,27.575 U18.3@62.975,26.6 62.975,25.55 R101.1@63.075,25.45 ; v1@63.425,31.675 63.425,32.525 C83.1@64.1,33.2 ; U18.9@64.2,28.125 U18.9@64.075,28 ; U18.9@64.625,28.575 U18.9@64.05,28 ; v1(64.75,28) U18.9@64.075,28 ; R98.1@67.15,32.15 v1(67.9,32.15) ; v1(63.3,28) U18.9@64.05,28 ; v1(63.3,28) U18.9@64.05,28 ; U18.9@64.05,28 U18.9@64.075,28 ; U18.9@64.05,28 U18.9@64.075,28
  Bottom Layer w0.5: R101.1@63.1,25.3 63.1,25.075 63.425,24.75 R100.1@64.1,24.75 65.475,24.75 C85.2@65.5,24.775 ; C88.1@64.95,22.575 65.625,22.575 66,22.95 C87.1@66.25,22.95 C86.1@67.1,22.95 C89.1@67.1,22.05
  Bottom Layer w0.6: C84.1@62.2,31.65 v1(63.45,31.65) ; L5.2@63.2,23.65 v1(63.975,23.65) ; v1(64.8,21.727) C88.1@64.8,22.55 64.875,22.625 v1(64.875,23.4) ; C85.2@65.675,24.6 v1(66.75,24.6)
BOOT0: R54.2 R55.2 U13.138 | length 3.2
  Top Layer w0.3: U13.138@41.575,50.05 43.6,50.05 R54.2@43.65,50.1 ; R54.2@43.65,50.05 R55.2@44.75,50.05
CODEC_CK: R23.1 TP14.1 U13.117 | length 77.5
  Top Layer w0.127: R23.1@13.4,73.4 13.4,73.925 13.55,74.075 14.5,74.075 14.971,74.546 23.971,74.546 26.25,76.825 28.5,76.825 29.092,76.233 39.683,76.233 v1(39.975,76.525) ; U13.117@41.575,39.55 v1(43.275,39.55) 44.067,39.55 44.421,39.904 44.435,39.904 44.862,40.331 45.412,40.331 46.194,41.113 46.194,41.6 46.444,41.85 TP14.1@47.95,41.85
  Bottom Layer w0.127: v1(39.975,76.525) 41.096,75.404 41.096,66.57 44.134,63.532 44.134,56.293 41.971,54.13 41.971,45.72 42.345,45.345 42.345,43.93 42.97,43.305 ; 42.975,43.3 42.97,43.305 ; v1@43.3,39.575 43.3,40.675 44.275,41.65 44.275,42.475 43.445,43.305 42.97,43.305
CODEC_EXT_SD: R22.1 TP5.1 U13.28 | length 38.7
  Top Layer w0.127: TP5.1@9.925,73.4 R22.1@12,73.4 ; R22.1@12.075,73.275 12.225,73.425 12.225,74.025 12.529,74.329 14.35,74.329 14.821,74.8 22.9,74.8 v1(23.6,75.5) ; U13.28@26.2,54.925 26.2,56.075 26.227,56.102 v1(26.376,56.102)
  Bottom Layer w0.127: v1(23.6,75.5) 24.25,74.85 25.975,74.85 26.225,74.6 26.4,74.425 26.4,72.75 26.175,72.525 25.275,71.625 25.275,65.95 25.8,65.425 25.8,57.875 26.375,57.3 v1@26.375,56.125 ; v1@26.376,56.125 v1@26.376,56.151
CODEC_INT: R29.1 TP8.1 U13.132 | length 60.5
  Top Layer w0.127: R29.1@10.35,69.45 8.75,69.45 8.025,68.725 TP8.1@8.025,65.575 8.025,64.368 9.185,63.208 11.485,63.208 13.568,61.125 16.775,61.125 17.15,61.5 19.738,61.5 20.525,62.287 20.788,62.55 22.425,62.55 24.51,64.635 25.503,64.635 25.848,64.979 28.637,64.979 28.681,64.935 36.165,64.935 v1(36.425,64.675) ; 37.316,51.516 39.338,51.516 40.221,50.633 40.221,49.645 40.575,49.291 40.575,47.35 40.875,47.05 U13.132@41.575,47.05
  Bottom Layer w0.127: v1(36.425,64.675) 36.425,63.75 35.735,63.06 35.735,52.975 36.844,51.865 36.844,51.556 v1@37.1,51.3
  other v1: 37.1,51.275
CODEC_MCK: R26.2 TP10.1 U13.37 | length 32.9
  Top Layer w0.127: v1(13.475,57.075) TP10.1@14.775,57.075 ; v1(17.25,53.55) 18.55,53.55 18.775,53.325 19.05,53.05 U13.37@20.325,53.05 ; R26.2@20.85,70.425 21.525,70.425 v1(21.925,70.825)
  Bottom Layer w0.127: v1(17.25,53.55) 17.275,53.55 v1@17.263,53.538 ; v1@17.275,53.525 15.05,53.525 13.475,55.1 v1(13.475,57.075) 13.475,59.675 17.579,63.779 21.735,63.779 22.491,64.535 22.603,64.535 22.95,64.881 22.95,68.4 21.925,69.425 v1(21.925,70.825)
CODEC_SD: R33.1 TP7.1 U13.29 | length 21.6
  Top Layer w0.127: R33.1@20.85,68.025 21.015,67.86 21.391,67.86 21.397,67.866 21.803,67.866 21.809,67.86 TP7.1@24.45,67.86 v1@25.84,67.86 ; U13.29@25.7,54.925 25.7,53.7 v1(25.725,53.675) ; v1(25.875,67.85) 25.865,67.86 v1@25.84,67.86 ; v1@25.9,67.85 25.875,67.825 v1@25.84,67.86
  Bottom Layer w0.127: v1(25.725,53.675) 26.812,54.762 ; v1@25.875,67.8 25.875,65.85 26.054,65.671 26.054,57.996 26.975,57.075 26.975,54.9 26.825,54.75 ; v1(25.875,67.85) 25.9,67.85 v1@25.9,67.8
